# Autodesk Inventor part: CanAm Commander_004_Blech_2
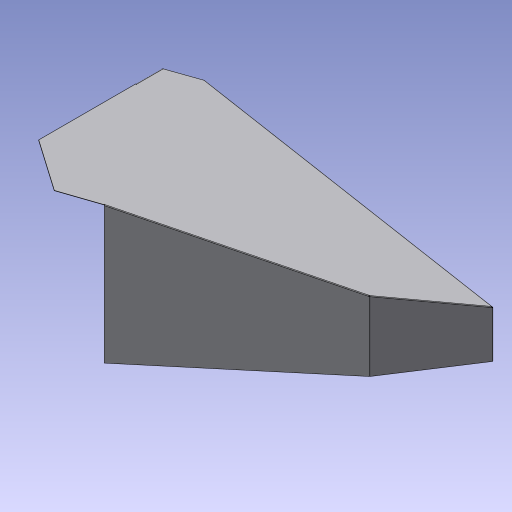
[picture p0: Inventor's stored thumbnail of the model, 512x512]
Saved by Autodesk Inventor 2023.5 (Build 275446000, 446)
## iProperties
Category: Vorlagen
Company: KAME engineering
Part Number: CanAm Commander_004_Blech_2
Material: Generisch
Document SubType Name: Modeling
Designer: wondraschek
Density: 1 g/cm^3
Appearance: Vorgabe
Created: 2025-04
Stärke: 0
Breite: 0
Höhe: 0
Länge: 0
da: 0
di: 0
Title: Bauteilvorlage
Author: KAME-JW
Comments: KAME engineering Lunzerstraße 89, 4030 Linz +43 732 6989 2474 www.kame.at
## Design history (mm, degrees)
derived "CanAm Commander_004_Blech.ipt"
feature "Volumenkörper4::CanAm Commander_004_Blech.ipt"
tag "Bezeichnung1"
node "Volumenkörper4"
feature "CanAm Commander_004_Blech.ipt_Körper"
other parameters: "Stärke" = 0 (computed from Stärke_1) [user parameter], "Breite" = 0 (computed from Breite_1) [user parameter], "Höhe" = 0 (computed from Höhe_1) [user parameter], "Länge" = 0 (computed from Länge_1) [user parameter], "da" = 0 (computed from da_1) [user parameter], "di" = 0 (computed from di_1) [user parameter], "Stärke_1" = 0, "Breite_1" = 0, "Höhe_1" = 0, "Länge_1" = 0, "da_1" = 0, "di_1" = 0
